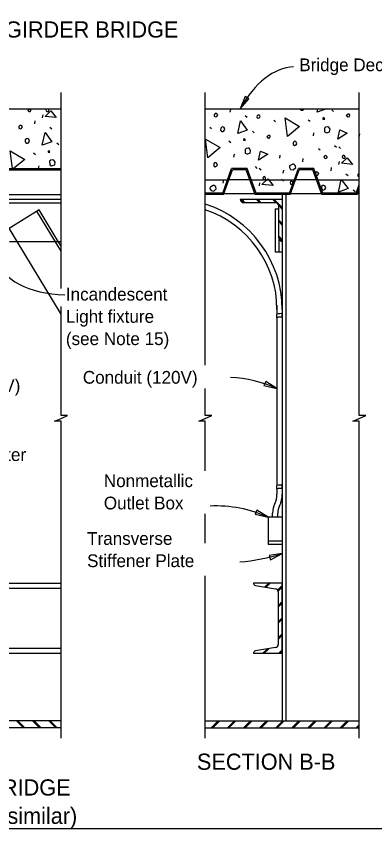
# Model space of a CAD drawing. Extents: x 112544 to 112597.1, y 111084 to 111107.1.
# Drawn here: x 112552.21 to 112556.46, y 111085.9 to 111095.54 of the extents above; entities that cross this region are included whole.
import ezdxf

# ---------------------------------------------------------------- set-up
doc = ezdxf.new("R2010")
doc.units = 0
for name, color, linetype in [('ActivePts-ConstElements', 7, 'Continuous'), ('Dimension', 7, 'Continuous'), ('Lighting', 7, 'Continuous'), ('Miscellaneous', 7, 'Continuous'), ('SteelGirder', 7, 'Continuous'), ('SteelGirder_h', 7, 'Continuous'), ('SupstrConc', 7, 'Continuous'), ('TextStructures', 7, 'Continuous')]:
    doc.layers.add(name, color=color, linetype=linetype)

msp = doc.modelspace()

# ---------------------------------------------------------------- linework, layer by layer
at = {"layer": 'ActivePts-ConstElements'}
msp.add_lwpolyline([(112543.9918, 111085.9039), (112574.7797, 111085.9039), (112574.7797, 111105.3634), (112543.9918, 111105.3634)], close=True, dxfattribs=at)
at = {"layer": 'Dimension'}
for points in [[(112552.7437, 111092.3104), (112552.7437, 111094.6352)], [(112554.4515, 111091.3997), (112554.4515, 111094.6352)], [(112556.2765, 111086.9751), (112556.2765, 111090.7348), (112556.199, 111090.7348), (112556.2765, 111090.7686), (112556.354, 111090.8023), (112556.2765, 111090.8023), (112556.2765, 111094.6352)], [(112552.7437, 111086.9751), (112552.7437, 111090.7348), (112552.6662, 111090.7348), (112552.7437, 111090.7686), (112552.8212, 111090.8023), (112552.7437, 111090.8023), (112552.7437, 111092.0947)], [(112554.4515, 111090.1478), (112554.4515, 111090.7348), (112554.374, 111090.7348), (112554.4515, 111090.7686), (112554.529, 111090.8023), (112554.4515, 111090.8023), (112554.4515, 111091.1216)], [(112554.4515, 111089.2891), (112554.4515, 111089.6353)], [(112554.4515, 111086.9751), (112554.4515, 111088.9017)]]:
    msp.add_lwpolyline(points, dxfattribs=at)
for points in [[(112554.8652, 111094.4391), (112554.9699, 111094.558), (112554.9249, 111094.5859)], [(112555.3018, 111091.1216), (112555.1678, 111091.2061), (112555.1474, 111091.1573)], [(112555.1976, 111089.5964), (112555.0635, 111089.6808), (112555.0432, 111089.632)], [(112555.3642, 111089.1651), (112555.2073, 111089.1434), (112555.2232, 111089.0929)]]:
    msp.add_lwpolyline(points, close=True, dxfattribs=at)
for centre, radius, start, end in [((112554.683, 111089.7634), 1.4925, 65.50737, 87.36586), ((112554.5788, 111088.2382), 1.4925, 65.50737, 92.69977), ((112554.6734, 111091.3555), 2.2968, 274.66721, 287.50633)]:
    msp.add_arc(centre, radius, start, end, dxfattribs=at)
for centre, major_axis, ratio, start_param, end_param in [((112555.6103, 111092.5703), (0.1111, -2.3674), 0.464296, 3.141604, 3.781059), ((112553.2613, 111093.1104), (1.3013, 0.4369), 0.58496, 3.141593, 4.152777)]:
    msp.add_ellipse(centre, major_axis=major_axis, ratio=ratio, start_param=start_param, end_param=end_param, dxfattribs=at)
at = {"layer": 'Lighting'}
for p, q in [((112555.3018, 111092.111), (112555.3018, 111092.0064)), ((112555.3018, 111091.9628), (112555.3018, 111089.9743)), ((112555.3018, 111089.9307), (112555.3018, 111089.869)), ((112555.3643, 111089.5964), (112555.1976, 111089.5964)), ((112555.1976, 111089.5964), (112555.1976, 111089.273)), ((112555.2497, 111089.5964), (112555.2497, 111089.6467)), ((112555.3122, 111089.5964), (112555.3122, 111089.6467)), ((112555.3643, 111089.3134), (112555.1976, 111089.3134)), ((112555.3643, 111089.273), (112555.1976, 111089.273))]:
    msp.add_line(p, q, dxfattribs=at)
for centre, radius, start, end in [((112554.0518, 111092.0589), 1.3125, 0.00119, 72.26682), ((112554.0518, 111092.0589), 1.25, 0, 71.34833), ((112555.0518, 111089.869), 0.25, 333.61151, 0), ((112555.0518, 111089.869), 0.3125, 333.61151, 0.00004), ((112555.4997, 111089.6467), 0.25, 153.61151, 179.99999), ((112555.4997, 111089.6467), 0.1875, 153.61151, 179.99999)]:
    msp.add_arc(centre, radius, start, end, dxfattribs=at)
at = {"layer": 'Miscellaneous'}
for p, q in [((112554.7479, 111094.4), (112554.7533, 111094.4377)), ((112555.9518, 111094.4276), (112555.9727, 111094.4073)), ((112552.524, 111094.3342), (112552.5301, 111094.3695)), ((112554.9238, 111094.3618), (112554.9496, 111094.3428)), ((112552.4325, 111094.2605), (112552.4379, 111094.2982)), ((112552.6084, 111094.2223), (112552.6341, 111094.2033)), ((112554.5059, 111094.2213), (112554.5256, 111094.2059)), ((112555.2649, 111094.3056), (112555.2853, 111094.2878)), ((112555.6724, 111094.3113), (112555.6957, 111094.2917)), ((112555.01, 111094.1752), (112555.031, 111094.155)), ((112555.7338, 111094.1207), (112555.7399, 111094.156)), ((112556.2762, 111094.1056), (112556.2816, 111094.1432)), ((112552.6946, 111094.0357), (112552.7155, 111094.0155)), ((112554.7306, 111094.0589), (112554.754, 111094.0393)), ((112555.7945, 111093.9713), (112555.8148, 111093.9535)), ((112555.9843, 111094.0066), (112556.0053, 111093.9864)), ((112556.0332, 111093.9887), (112556.0541, 111093.9684)), ((112552.4152, 111093.9194), (112552.4385, 111093.8998)), ((112554.792, 111093.8683), (112554.7981, 111093.9036)), ((112555.3344, 111093.8532), (112555.3398, 111093.8909)), ((112555.6068, 111093.8123), (112555.6122, 111093.85)), ((112552.4769, 111093.7309), (112552.4827, 111093.7641)), ((112555.0426, 111093.7543), (112555.0635, 111093.734)), ((112555.9433, 111093.7058), (112555.9487, 111093.7435)), ((112556.0349, 111093.7795), (112556.0409, 111093.8148)), ((112547.9235, 111093.7309), (112552.7436, 111093.7309)), ((112547.9277, 111093.7153), (112552.7436, 111093.7153)), ((112554.6584, 111093.4391), (112554.7646, 111093.7309)), ((112554.6693, 111093.4235), (112554.7755, 111093.7153)), ((112554.9479, 111093.7309), (112554.7646, 111093.7309)), ((112554.9369, 111093.7153), (112554.7755, 111093.7153)), ((112555.0431, 111093.4235), (112554.9369, 111093.7153)), ((112555.054, 111093.4391), (112554.9479, 111093.7309)), ((112555.0914, 111093.7363), (112555.1123, 111093.7161)), ((112555.3768, 111093.6756), (112555.3829, 111093.7109)), ((112555.4488, 111093.4391), (112555.555, 111093.7309)), ((112555.4597, 111093.4235), (112555.5659, 111093.7153)), ((112555.7383, 111093.7309), (112555.555, 111093.7309)), ((112555.7274, 111093.7153), (112555.5659, 111093.7153)), ((112555.8336, 111093.4235), (112555.7274, 111093.7153)), ((112555.8445, 111093.4391), (112555.7383, 111093.7309)), ((112556.1192, 111093.6675), (112556.145, 111093.6485)), ((112554.665, 111093.56), (112554.6704, 111093.5976)), ((112555.0931, 111093.5271), (112555.0992, 111093.5624)), ((112555.3568, 111093.6056), (112555.3801, 111093.5859)), ((112556.2054, 111093.481), (112556.2264, 111093.4607)), ((112556.2392, 111093.4391), (112556.2765, 111093.5414)), ((112556.2502, 111093.4235), (112556.2765, 111093.4958)), ((112547.2516, 111093.4236), (112552.7436, 111093.4236)), ((112554.6584, 111093.4391), (112554.4515, 111093.4391)), ((112554.6693, 111093.4235), (112554.4515, 111093.4235)), ((112554.9071, 111093.3269), (112554.8655, 111093.3686)), ((112554.9248, 111093.3269), (112554.8832, 111093.3686)), ((112555.4597, 111093.4235), (112555.0431, 111093.4235)), ((112555.4488, 111093.4391), (112555.054, 111093.4391)), ((112555.0981, 111093.3269), (112555.0564, 111093.3686)), ((112555.1157, 111093.3269), (112555.0741, 111093.3686)), ((112555.2914, 111093.3245), (112555.2473, 111093.3686)), ((112555.3643, 111093.2693), (112555.265, 111093.3686)), ((112556.2502, 111093.4235), (112555.8336, 111093.4235)), ((112556.2392, 111093.4391), (112555.8445, 111093.4391)), ((112555.3643, 111093.2517), (112555.3199, 111093.296)), ((112555.3643, 111093.0784), (112555.3226, 111093.1201)), ((112555.3643, 111093.0607), (112555.3226, 111093.1024)), ((112555.3643, 111092.8875), (112555.3226, 111092.9292)), ((112555.3643, 111092.8698), (112555.3226, 111092.9115)), ((112555.0243, 111088.8108), (112555.03, 111088.8165)), ((112555.157, 111088.7703), (112555.2032, 111088.8165)), ((112555.1722, 111088.7678), (112555.2209, 111088.8165)), ((112555.3095, 111088.7319), (112555.3643, 111088.7866)), ((112555.3149, 111088.7196), (112555.3643, 111088.769)), ((112555.3163, 111088.5478), (112555.3643, 111088.5957)), ((112555.3163, 111088.5301), (112555.3643, 111088.578)), ((112555.3163, 111088.3569), (112555.3643, 111088.4048)), ((112555.3163, 111088.3392), (112555.3643, 111088.3871)), ((112555.3163, 111088.166), (112555.3643, 111088.2139)), ((112555.3163, 111088.1483), (112555.3643, 111088.1962)), ((112555.1336, 111087.9832), (112555.1843, 111088.0339)), ((112555.1512, 111087.9832), (112555.2054, 111088.0374)), ((112555.3245, 111087.9832), (112555.3643, 111088.023)), ((112555.3422, 111087.9832), (112555.3643, 111088.0053)), ((112552.2981, 111087.0979), (112552.2149, 111087.1812)), ((112552.3158, 111087.0979), (112552.2325, 111087.1812)), ((112552.4891, 111087.0979), (112552.4058, 111087.1812)), ((112552.5067, 111087.0979), (112552.4235, 111087.1812)), ((112552.68, 111087.0979), (112552.5967, 111087.1812)), ((112552.6977, 111087.0979), (112552.6144, 111087.1812)), ((112554.5232, 111087.0979), (112554.6065, 111087.1812)), ((112554.5409, 111087.0979), (112554.6241, 111087.1812)), ((112554.7141, 111087.0979), (112554.7974, 111087.1812)), ((112554.7318, 111087.0979), (112554.8151, 111087.1812)), ((112554.905, 111087.0979), (112554.9883, 111087.1812)), ((112554.9227, 111087.0979), (112555.006, 111087.1812)), ((112555.0959, 111087.0979), (112555.1792, 111087.1812)), ((112555.1136, 111087.0979), (112555.1969, 111087.1812)), ((112555.2868, 111087.0979), (112555.3701, 111087.1812)), ((112555.3045, 111087.0979), (112555.3878, 111087.1812)), ((112555.4778, 111087.0979), (112555.561, 111087.1812)), ((112555.4954, 111087.0979), (112555.5787, 111087.1812)), ((112555.6687, 111087.0979), (112555.752, 111087.1812)), ((112555.6864, 111087.0979), (112555.7696, 111087.1812)), ((112555.8596, 111087.0979), (112555.9429, 111087.1812)), ((112555.8773, 111087.0979), (112555.9606, 111087.1812)), ((112556.0505, 111087.0979), (112556.1338, 111087.1812)), ((112556.0682, 111087.0979), (112556.1515, 111087.1812)), ((112556.2414, 111087.0979), (112556.2765, 111087.1329)), ((112556.2591, 111087.0979), (112556.2765, 111087.1153))]:
    msp.add_line(p, q, dxfattribs=at)
for points in [[(112552.3479, 111094.4216), (112552.3621, 111094.4073), (112552.3772, 111094.4088), (112552.3849, 111094.4186), (112552.3836, 111094.4235), (112552.3749, 111094.4366), (112552.3686, 111094.4392)], [(112552.3617, 111094.4392), (112552.3556, 111094.4315), (112552.3479, 111094.4216)], [(112552.5535, 111094.3499), (112552.6239, 111094.4154), (112552.6865, 111094.3364), (112552.5535, 111094.3499)], [(112552.5739, 111094.4392), (112552.5714, 111094.4375), (112552.563, 111094.4301), (112552.5669, 111094.4156)], [(112552.5669, 111094.4156), (112552.5767, 111094.4079), (112552.5901, 111094.4063), (112552.5985, 111094.4137), (112552.5983, 111094.424), (112552.5926, 111094.4355), (112552.5899, 111094.4392)], [(112555.5764, 111094.4392), (112555.5856, 111094.4226), (112555.6031, 111094.4247), (112555.6146, 111094.4304), (112555.6197, 111094.4392)], [(112555.7782, 111094.3992), (112555.7867, 111094.4392)], [(112555.8896, 111094.4392), (112555.7782, 111094.3992)], [(112554.5592, 111094.3702), (112554.5589, 111094.352), (112554.5766, 111094.3438), (112554.5905, 111094.3501), (112554.6017, 111094.366), (112554.5936, 111094.3768), (112554.5869, 111094.3828), (112554.5759, 111094.385), (112554.5711, 111094.3837), (112554.5592, 111094.3702)], [(112555.0655, 111094.335), (112555.0717, 111094.3315), (112555.0874, 111094.3306), (112555.1, 111094.3417), (112555.1029, 111094.3502), (112555.0942, 111094.3634), (112555.0736, 111094.3631), (112555.0652, 111094.3556), (112555.0629, 111094.3447), (112555.0655, 111094.335)], [(112555.4252, 111094.1131), (112555.3973, 111094.3333), (112555.5694, 111094.2319), (112555.4252, 111094.1131)], [(112555.8463, 111094.3191), (112555.8675, 111094.317), (112555.8649, 111094.3267), (112555.8569, 111094.3374), (112555.8461, 111094.3294), (112555.8463, 111094.3191)], [(112556.1264, 111094.3553), (112556.1448, 111094.3447), (112556.1593, 111094.3486), (112556.1644, 111094.3681), (112556.1454, 111094.3811), (112556.137, 111094.3737), (112556.128, 111094.3687), (112556.1264, 111094.3553), (112556.1251, 111094.3601)], [(112552.2438, 111094.2307), (112552.2435, 111094.2125), (112552.2612, 111094.2043), (112552.275, 111094.2106), (112552.2863, 111094.2265), (112552.2782, 111094.2373), (112552.2714, 111094.2433), (112552.2605, 111094.2455), (112552.2557, 111094.2442), (112552.2438, 111094.2307)], [(112554.6352, 111094.212), (112554.6338, 111094.1883), (112554.6438, 111094.1703), (112554.6614, 111094.1724), (112554.6728, 111094.178), (112554.6834, 111094.1964), (112554.6776, 111094.2181), (112554.6598, 111094.2263), (112554.6478, 111094.2231), (112554.6352, 111094.212)], [(112554.8364, 111094.1468), (112554.8685, 111094.2978), (112554.9498, 111094.1875), (112554.8364, 111094.1468)], [(112555.8651, 111094.2102), (112555.8664, 111094.1666), (112555.8872, 111094.1566), (112555.8993, 111094.1599), (112555.9258, 111094.167), (112555.9302, 111094.1992), (112555.9158, 111094.2238), (112555.897, 111094.2265), (112555.8776, 111094.2213), (112555.8651, 111094.2102)], [(112552.521, 111094.0073), (112552.553, 111094.1583), (112552.6343, 111094.048), (112552.521, 111094.0073)], [(112555.1847, 111094.103), (112555.203, 111094.0924), (112555.2175, 111094.0962), (112555.2227, 111094.1157), (112555.2036, 111094.1287), (112555.1953, 111094.1213), (112555.1863, 111094.1163), (112555.1847, 111094.103), (112555.1834, 111094.1078)], [(112556.0237, 111094.0819), (112556.0468, 111094.189), (112556.1341, 111094.1529), (112556.0237, 111094.0819)], [(112552.3198, 111094.0725), (112552.3184, 111094.0488), (112552.3284, 111094.0308), (112552.3459, 111094.0329), (112552.3574, 111094.0385), (112552.368, 111094.0569), (112552.3621, 111094.0786), (112552.3444, 111094.0868), (112552.3323, 111094.0836), (112552.3198, 111094.0725)], [(112554.4835, 111093.8607), (112554.4555, 111094.081), (112554.6276, 111093.9796), (112554.4835, 111093.8607)], [(112554.9045, 111094.0667), (112554.9258, 111094.0646), (112554.9232, 111094.0743), (112554.9151, 111094.0851), (112554.9043, 111094.077), (112554.9045, 111094.0667)], [(112555.4951, 111094.036), (112555.4948, 111094.0178), (112555.5114, 111094.0041), (112555.527, 111094.0135), (112555.5371, 111094.024), (112555.5339, 111094.0361), (112555.5245, 111094.0517), (112555.5081, 111094.055), (112555.4955, 111094.0439), (112555.4951, 111094.036)], [(112552.1668, 111093.7309), (112552.1401, 111093.9415), (112552.3122, 111093.8401), (112552.1798, 111093.7309)], [(112552.5891, 111093.9272), (112552.6103, 111093.9251), (112552.6077, 111093.9348), (112552.5997, 111093.9456), (112552.5889, 111093.9375), (112552.5891, 111093.9272)], [(112554.9233, 111093.9579), (112554.9246, 111093.9142), (112554.9454, 111093.9043), (112554.9575, 111093.9075), (112554.9841, 111093.9146), (112554.9884, 111093.9468), (112554.974, 111093.9715), (112554.9552, 111093.9742), (112554.9359, 111093.969), (112554.9233, 111093.9579)], [(112555.0819, 111093.8296), (112555.105, 111093.9367), (112555.1923, 111093.9005), (112555.0819, 111093.8296)], [(112552.6079, 111093.8184), (112552.6092, 111093.7747), (112552.63, 111093.7648), (112552.6421, 111093.768), (112552.6686, 111093.7751), (112552.673, 111093.8073), (112552.6586, 111093.832), (112552.6397, 111093.8347), (112552.6204, 111093.8295), (112552.6079, 111093.8184)], [(112555.8587, 111093.8669), (112555.8729, 111093.8526), (112555.8881, 111093.854), (112555.8958, 111093.8639), (112555.8945, 111093.8687), (112555.8858, 111093.8819), (112555.8742, 111093.8865), (112555.8665, 111093.8767), (112555.8587, 111093.8669)], [(112556.0643, 111093.7951), (112556.1348, 111093.8606), (112556.1973, 111093.7816), (112556.0643, 111093.7951)], [(112556.0778, 111093.8609), (112556.0876, 111093.8531), (112556.101, 111093.8515), (112556.1093, 111093.859), (112556.1091, 111093.8693), (112556.1035, 111093.8807), (112556.0954, 111093.8915), (112556.0822, 111093.8828), (112556.0739, 111093.8753), (112556.0778, 111093.8609)], [(112554.5533, 111093.7837), (112554.553, 111093.7655), (112554.5696, 111093.7518), (112554.5852, 111093.7612), (112554.5953, 111093.7716), (112554.5921, 111093.7837), (112554.5827, 111093.7993), (112554.5663, 111093.8027), (112554.5538, 111093.7916), (112554.5533, 111093.7837)], [(112555.449, 111093.7442), (112555.4627, 111093.722), (112555.495, 111093.7176), (112555.5242, 111093.7436), (112555.5178, 111093.7678), (112555.5005, 111093.7838), (112555.4878, 111093.783), (112555.4674, 111093.7724), (112555.4517, 111093.763), (112555.449, 111093.7442)], [(112555.7671, 111093.6518), (112555.772, 111093.6495), (112555.7859, 111093.6558), (112555.7971, 111093.6718), (112555.7891, 111093.6826), (112555.7823, 111093.6885), (112555.7713, 111093.6908), (112555.7665, 111093.6895), (112555.7572, 111093.6789)], [(112556.2765, 111093.6689), (112556.269, 111093.6688), (112556.2606, 111093.6614), (112556.2584, 111093.6504), (112556.261, 111093.6408)], [(112555.1225, 111093.5428), (112555.193, 111093.6083), (112555.2556, 111093.5293), (112555.1225, 111093.5428)], [(112555.136, 111093.6085), (112555.1458, 111093.6008), (112555.1592, 111093.5992), (112555.1675, 111093.6066), (112555.1674, 111093.6169), (112555.1617, 111093.6283), (112555.1537, 111093.6391), (112555.1405, 111093.6304), (112555.1321, 111093.623), (112555.136, 111093.6085)], [(112555.4594, 111093.5606), (112555.4633, 111093.5461), (112555.476, 111093.5469), (112555.4874, 111093.5526), (112555.4932, 111093.5696), (112555.4864, 111093.5756), (112555.4748, 111093.5803), (112555.4603, 111093.5764), (112555.4594, 111093.5606)], [(112556.0319, 111093.4526), (112556.0639, 111093.6035), (112556.1452, 111093.4933), (112556.0319, 111093.4526)], [(112556.261, 111093.6408), (112556.2671, 111093.6372), (112556.2765, 111093.6367)], [(112554.5073, 111093.4918), (112554.521, 111093.4696), (112554.5532, 111093.4653), (112554.5825, 111093.4913), (112554.576, 111093.5154), (112554.5587, 111093.5315), (112554.546, 111093.5307), (112554.5256, 111093.52), (112554.51, 111093.5107), (112554.5073, 111093.4918)], [(112555.8306, 111093.5177), (112555.8292, 111093.494), (112555.8392, 111093.476), (112555.8568, 111093.4781), (112555.8682, 111093.4838), (112555.8788, 111093.5021), (112555.873, 111093.5239), (112555.8553, 111093.5321), (112555.8432, 111093.5288), (112555.8306, 111093.5177)]]:
    msp.add_lwpolyline(points, dxfattribs=at)
at = {"layer": 'SteelGirder'}
for p, q in [((112554.9797, 111093.5979), (112554.7327, 111093.5979)), ((112555.7701, 111093.5979), (112555.5232, 111093.5979)), ((112552.1214, 111093.3686), (112552.7436, 111093.3686)), ((112555.0403, 111093.4312), (112554.6721, 111093.4312)), ((112554.8643, 111093.3686), (112555.3643, 111093.3686)), ((112555.3643, 111093.4235), (112555.3643, 111087.1812)), ((112555.3643, 111093.3686), (112555.3643, 111092.8686)), ((112555.406, 111093.4235), (112555.406, 111087.1812)), ((112555.8308, 111093.4312), (112555.4625, 111093.4312)), ((112556.2765, 111093.4312), (112556.2529, 111093.4312)), ((112552.1214, 111093.3269), (112552.7436, 111093.3269)), ((112555.2809, 111093.3269), (112554.9059, 111093.3269)), ((112555.3226, 111092.9103), (112555.3226, 111093.2853)), ((112555.2809, 111093.254), (112555.2809, 111092.7442)), ((112555.2809, 111093.254), (112555.3226, 111093.254)), ((112555.3226, 111092.9103), (112555.3226, 111092.7442)), ((112552.1318, 111092.8685), (112552.7436, 111092.8685)), ((112552.7436, 111092.0061), (112552.2219, 111092.8685)), ((112552.7436, 111092.8114), (112552.7091, 111092.8685)), ((112555.2809, 111092.7442), (112555.3643, 111092.7442)), ((112555.2966, 111092.0035), (112555.2966, 111091.9628)), ((112555.3591, 111092.0197), (112555.3643, 111092.0197)), ((112555.3591, 111092.0197), (112555.3591, 111091.9703)), ((112555.3591, 111091.9791), (112555.3643, 111091.9791)), ((112555.3591, 111089.9876), (112555.3643, 111089.9876)), ((112555.3591, 111089.9876), (112555.3591, 111089.9382)), ((112555.2966, 111089.9713), (112555.2966, 111089.9307)), ((112555.3591, 111089.9469), (112555.3643, 111089.9469)), ((112547.9346, 111088.8164), (112552.7436, 111088.8164)), ((112547.9346, 111088.754), (112552.7436, 111088.754)), ((112555.3643, 111088.8165), (112555.0226, 111088.8165)), ((112555.0465, 111088.7883), (112555.285, 111088.7493)), ((112555.3643, 111087.9832), (112555.3643, 111088.8165)), ((112555.3163, 111088.7124), (112555.3163, 111088.0874)), ((112547.9346, 111088.0457), (112552.7436, 111088.0457)), ((112547.9346, 111087.9832), (112552.7436, 111087.9832)), ((112555.0226, 111087.9832), (112555.3643, 111087.9832)), ((112555.285, 111088.0504), (112555.0465, 111088.0114)), ((112552.7436, 111087.0979), (112547.7292, 111087.0979)), ((112552.7436, 111087.1812), (112551.96, 111087.1812)), ((112554.4515, 111087.1812), (112556.2765, 111087.1812)), ((112554.4515, 111087.0979), (112556.2765, 111087.0979))]:
    msp.add_line(p, q, dxfattribs=at)
for centre, radius, start, end in [((112554.9059, 111093.3686), 0.0417, 180, 270), ((112555.2809, 111093.2853), 0.0417, 0, 90), ((112555.3643, 111092.9103), 0.0417, 180, 270), ((112555.0512, 111088.8165), 0.0286, 180, 260.5), ((112555.2788, 111088.7124), 0.0375, 360, 80.5), ((112555.2788, 111088.0874), 0.0375, 279.5, 360), ((112555.0512, 111087.9832), 0.0286, 99.5, 180)]:
    msp.add_arc(centre, radius, start, end, dxfattribs=at)
for centre, ratio, start_param, end_param in [((112555.3591, 111092.0035), 0.119608, 1.570506, 3.140799), ((112555.3591, 111091.9628), 0.119608, 1.570506, 3.552397), ((112555.3643, 111091.9628), 0.111403, 1.571206, 3.141305), ((112555.3591, 111089.9307), 0.119608, 1.570506, 3.552397), ((112555.3591, 111089.9713), 0.119608, 1.570506, 3.140799), ((112555.3643, 111089.9307), 0.111403, 1.571206, 3.141305)]:
    msp.add_ellipse(centre, major_axis=(0.0625, 0), ratio=ratio, start_param=start_param, end_param=end_param, dxfattribs=at)
at = {"layer": 'SteelGirder_h'}
for p, q in [((112554.4515, 111093.5979), (112554.7327, 111093.5979)), ((112554.9797, 111093.5979), (112555.5232, 111093.5979)), ((112555.7701, 111093.5979), (112556.2765, 111093.5979)), ((112554.4515, 111093.4312), (112554.6721, 111093.4312)), ((112555.0403, 111093.4312), (112555.4625, 111093.4312)), ((112555.8308, 111093.4312), (112556.2529, 111093.4312)), ((112552.4826, 111093.2429), (112552.1286, 111093.0227)), ((112552.7436, 111092.7511), (112552.4573, 111093.2245)), ((112552.7091, 111092.8685), (112552.4839, 111093.2407)), ((112552.2219, 111092.8685), (112552.1273, 111093.0249))]:
    msp.add_line(p, q, dxfattribs=at)
at = {"layer": 'SupstrConc'}
for p, q in [((112544.2555, 111094.4392), (112552.7436, 111094.4392)), ((112554.4515, 111094.4392), (112556.2765, 111094.4392))]:
    msp.add_line(p, q, dxfattribs=at)

# ---------------------------------------------------------------- texts
at = {"layer": 'Dimension'}
for s, height, p in [('Incandescent', 0.1512, (112552.8004, 111092.1661)), ('Light fixture', 0.1512, (112552.8004, 111091.9021)), ('(see Note 15)', 0.1512, (112552.8004, 111091.6381)), ('Conduit (120V)', 0.1512, (112550.9012, 111091.0823)), ('Mini Power Center', 0.1512, (112550.6663, 111090.2636)), ('Nonmetallic', 0.1512, (112553.25, 111089.9536)), ('Outlet Box', 0.1512, (112553.25, 111089.6896)), ('Transverse', 0.1512, (112553.0517, 111089.2691)), ('Stiffener Plate', 0.1512, (112553.0517, 111089.0051)), ('LIGHTING DETAILS FOR STEEL BOX GIRDER BRIDGE', 0.192, (112546.265, 111086.296)), ('(Cross Frame section shown, other Transverse Stiffener sections similar)', 0.192, (112544.6451, 111085.96))]:
    msp.add_text(s, height=height, dxfattribs=at).set_placement(p)
at = {"layer": 'TextStructures'}
for s, height, p in [('LIGHTING DETAILS FOR CONCRETE BOX GIRDER BRIDGE', 0.192, (112546.9154, 111095.285)), ('Bridge Deck', 0.1512, (112555.5657, 111094.8861)), ('Conduit (120V)', 0.1512, (112553.0012, 111091.1802)), ('SECTION B-B', 0.192, (112554.3533, 111086.6013))]:
    msp.add_text(s, height=height, dxfattribs=at).set_placement(p)

doc.saveas('drawing.dxf')
